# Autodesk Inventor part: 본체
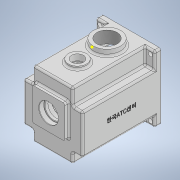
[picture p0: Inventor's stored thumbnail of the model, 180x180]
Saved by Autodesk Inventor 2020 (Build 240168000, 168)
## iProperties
Created: 2022-01
Part Number: 본체
Material: 일반
Document SubType Name: Modeling
Designer: user
Density: 1 g/cm^3
Appearance: 기본값
Author: user
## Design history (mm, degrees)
sketch "스케치21"
  geometry: 1 further point
sketch "스케치30"
  geometry: L1 (49, -55)-(-49, -55); L2 (-49, -55)-(-49, 55); L3 (-49, 55)-(49, 55); L4 (49, 55)-(49, -55); L5 (49, -55)-(-49, 55); L6 (-49, -55)-(49, 55); 1 further point
  constraints: 12 end point, 2 midpoint, 2 parallel, 1 horizontal, 1 perpendicular
  dimensions: "d101" = 98 distance of L2.end L3.end; "d102" = 110 distance of L1.end L2.end
extrude "돌출16" new body sketch "스케치30" stored distance "d103" = 130; taper "d104" = 0 deg
sketch "스케치31" dims "d106" = 84
  geometry: L1 (49, -55)-(-49, -55) reference; L2 (0, -55)-(0, -5); L3 (0, -5)-(0, 45); L4 (0, 45)-(-23, 45); L5 (-23, 45)-(23, 45); L6 (23, 45)-(23, 30.143); L7 (23, 30.143)-(-23, 30.143); L8 (-23, 30.143)-(-23, 45); L9 (26, 27.143)-(26, 48); L10 (26, 48)-(-26, 48); L11 (-26, 48)-(-26, 27.143); L12 (-26, 27.143)-(26, 27.143); C1 r 45 at (0, -5); 3 further points
  constraints: 22 end point, 4 parallel, 3 perpendicular, 2 vertical, 1 centre point, 1 coincident, 1 horizontal, 1 midpoint, 6 other
  dimensions: "d105" = 50 distance of L2.start L2.end; "d107" = 50 distance of L3.start L3.end; "d108" = 23 distance of L3.end L4.end; "d109" = 46 distance of L6.end L7.end; "d110" = 3 distance between parallel lines of L6 L9; "d111" = 3 dimension on C1
extrude "돌출17" cut sketch "스케치31" distance "d112" = 9; taper "d113" = 0 deg
sketch "스케치32" dims "d115" = 84
  geometry: L1 (-49, -55)-(49, -55) reference; L2 (0, -55)-(0, -5); L3 (0, -5)-(0, 45); L4 (0, 45)-(-23, 45); L5 (-23, 45)-(23, 45); L6 (23, 45)-(23, 30.143); L7 (23, 30.143)-(-23, 30.143); L8 (-23, 30.143)-(-23, 45); 3 further points
  constraints: 14 end point, 2 parallel, 2 perpendicular, 2 vertical, 1 coincident, 1 horizontal, 1 midpoint, 3 other
  dimensions: "d114" = 50 distance of L2.start L2.end; "d116" = 50 distance of L3.start L3.end; "d117" = 23 distance of L3.end L4.end; "d118" = 46 distance of L6.end L7.end
extrude "돌출18" cut sketch "스케치32" distance "d119" = 112; taper "d120" = 0 deg
sketch "스케치33"
  geometry: L1 (-49, -55)-(49, -55) reference; L2 (0, -55)-(0, -5); L3 (0, -5)-(0, 6); L4 (0, -5)-(0, -25); C1 r 21 at (0, 6); C2 r 15 at (0, -25); 3 further points
  constraints: 6 end point, 2 centre point, 2 coincident, 2 point on line, 1 midpoint, 1 vertical
  dimensions: "d121" = 50 distance of L2.start L2.end; "d122" = 11 distance of L2.end L3.end; "d123" = 20 distance of L2.end L4.end; "d124" = 42 diameter of C1; "d125" = 30 diameter of C2
extrude "돌출19" join sketch "스케치33" distance "d126" = 7; taper "d127" = 0 deg
sketch "스케치34"
  geometry: L1 (-49, 55)-(-49, -55) reference; L2 (-49, 55)-(-33, 55); L3 (-33, 55)-(-33, 28); L4 (-33, 28)-(-49, 28); L5 (-49, 28)-(-49, 55); L6 (-49, -55)-(49, -55) reference; L7 (-49, -55)-(-33, -55); L8 (-33, -55)-(-33, -38); L9 (-33, -38)-(-49, -38); L10 (-49, -38)-(-49, -55); L11 (49, -55)-(33, -55); L12 (33, -55)-(33, -38); L13 (33, -38)-(49, -38); L14 (49, -38)-(49, -55); L15 (49, 55)-(-49, 55) reference; L16 (49, 55)-(33, 55); L17 (33, 55)-(33, 28); L18 (33, 28)-(49, 28); L19 (49, 28)-(49, 55); 6 further points
  constraints: 32 end point, 8 parallel, 4 horizontal, 4 perpendicular
  dimensions: "d128" = 16 distance of L3.end L4.end; "d129" = 27 distance of L2.end L3.end; "d130" = 16 distance of L9.end L8.end; "d131" = 17 distance of L8.end L7.end; "d132" = 16 distance of L12.end L13.end; "d133" = 17 distance of L11.end L12.end; "d134" = 16 distance of L18.end L17.end; "d135" = 27 distance of L17.end L16.end
extrude "돌출20" cut sketch "스케치34" distance "d136" = 120; taper "d137" = 0 deg
sketch "스케치35"
  geometry: L1 (98, 0)-(0, 0) reference; L2 (49, 0)-(49, -40); L3 (49, -40)-(49, -89); C1 r 15 at (49, -89); C2 r 22.5 at (49, -40); 1 further point
  constraints: 4 end point, 2 centre point, 2 coincident, 1 midpoint, 1 point on line, 1 vertical
  dimensions: "d138" = 40 distance of L2.start L2.end; "d139" = 49 distance of L2.end L3.end; "d140" = 30 diameter of C1; "d141" = 45 diameter of C2
extrude "돌출21" join sketch "스케치35" distance "d142" = 5; taper "d143" = 0 deg
extrude "돌출22" join sketch "스케치35" distance "d144" = 10; taper "d145" = 0 deg
sketch "스케치36"
  geometry: C1 r 15 at (0, 0) reference; C2 r 10 at (0, 0); 1 further point
  constraints: 1 centre point, 1 coincident
  dimensions: "d146" = 20 diameter of C2
extrude "돌출23" cut sketch "스케치36" distance "d147" = 20; taper "d148" = 0 deg
sketch "스케치37"
  geometry: C1 r 10 at (23, 80) reference; C2 r 15 at (23, 80); 1 further point
  constraints: 1 centre point, 1 coincident
  dimensions: "d149" = 30 diameter of C2
extrude "돌출24" cut sketch "스케치37" distance "d150" = 5; taper "d151" = 0 deg
sketch "스케치38"
  geometry: 1 further point
sketch "스케치39"
  geometry: C1 r 22.5 at (0, 0) reference; 2 further points
  constraints: 1 coincident
hole "구멍4" sketch "스케치39" at (0, 0) diameter "d152" = 33.376; stored, may be unused: countersink angle "d156" = 90 deg, drill point angle "d158" = 118 deg; dims "d153" = 70, "d154" = 4, "d155" = 2, "d157" = 77.3
sketch "스케치40" dims "d162" = 8
  geometry: L1 (-49, -55)-(49, -55) reference; L2 (0, -55)-(0, -5); L3 (36, -1)-(41.644, -1); L4 (4, -9)-(-4, -9); L5 (-4, -9)-(-4, -1); L6 (-4, -1)-(4, -1); L7 (4, -1)-(4, -9); L8 (4, -9)-(-4, -1); L9 (-4, -9)-(4, -1); L10 (-4, -1)-(-47.386, -1); L11 (-4, -9)-(-49, -9); L12 (-49, -38)-(-49, 28) reference; L13 (4, -9)-(44.822, -9); L14 (4, -1)-(44.822, -1); C1 r 4 at (-36, -5); C2 r 42 at (0, -5); A1 r 36 centre (0, -5) between (-36, -5) and (36, -5); A2 r 45 centre (0, -5) between (-26, 31.729) and (26, 31.729) reference; A3 r 42 centre (0, -5) between (-23, 30.143) and (23, 30.143) reference; 7 further points
  constraints: 24 end point, 5 horizontal, 4 point on circle, 3 centre point, 3 midpoint, 3 point on line, 2 coincident, 2 horizontal alignment, 2 parallel, 1 concentric, 1 perpendicular, 1 vertical, 3 other
  dimensions: "d159" = 50 distance of L2.start L2.end; "d160" = 72 diameter of A1; "d161" = 8 diameter of C1; "d163" = 8 distance of L5.end L6.end; "d164" = 8 distance of L4.end L5.end
extrude "돌출25" join sketch "스케치40" distance "d165" = 121; taper "d166" = 0 deg
sketch "스케치41"
  geometry: L1 (42, -48)-(-42, -48); L2 (-42, -48)-(-42, 48); L3 (-42, 48)-(42, 48); L4 (42, 48)-(42, -48); L5 (42, -48)-(-42, 48); L6 (-42, -48)-(42, 48); 1 further point
  constraints: 12 end point, 2 midpoint, 2 parallel, 1 horizontal, 1 perpendicular
  dimensions: "d167" = 84 distance of L2.end L3.end; "d168" = 96 distance of L1.end L2.end
hole "구멍5" sketch "스케치41" at (-42, 48), (-42, -48), (42, -48), (42, 48) diameter "d169" = 7; stored, may be unused: countersink angle "d173" = 90 deg, drill point angle "d175" = 118 deg; dims "d170" = 70, "d171" = 4, "d172" = 2, "d174" = 77.3
sketch "스케치42"
  geometry: A1 r 4 centre (-36, -5) between (-36, -9) and (-36, -1) reference; A2 r 4 centre (36, -5) between (36, -1) and (36, -9) reference; 3 further points
  constraints: 2 coincident
hole "구멍6" sketch "스케치42" at (-36, -5), (36, -5) diameter "d176" = 3.242; stored, may be unused: countersink angle "d180" = 90 deg, drill point angle "d182" = 118 deg; dims "d177" = 7, "d178" = 4, "d179" = 2, "d181" = 9
sketch "스케치46"
  geometry: A1 r 21 centre (0, 6) between (8.978, -12.984) and (-8.978, -12.984) reference; 2 further points
  constraints: 1 coincident
hole "구멍7" sketch "스케치46" at (0, 6) diameter "d188" = 28; stored, may be unused: countersink angle "d192" = 90 deg, drill point angle "d194" = 118 deg; dims "d189" = 7, "d190" = 35, "d191" = 10, "d193" = 9
sketch "스케치47"
  geometry: A1 r 15 centre (0, -25) between (-8.978, -12.984) and (8.978, -12.984) reference; 2 further points
  constraints: 1 coincident
hole "구멍8" sketch "스케치47" at (0, -25) diameter "d195" = 19; stored, may be unused: countersink angle "d199" = 90 deg, drill point angle "d201" = 0 deg; dims "d196" = 7, "d197" = 22, "d198" = 7, "d200" = 10
sketch "스케치49"
  geometry: L1 (-27, -21)-(27, -21); L2 (27, -21)-(27, 33); L3 (27, 33)-(-27, 33); L4 (-27, 33)-(-27, -21); L5 (-27, -21)-(27, 33); L6 (27, -21)-(-27, 33); C1 r 16 at (0, 6) reference; 1 further point
  constraints: 12 end point, 2 midpoint, 2 parallel, 1 horizontal, 1 perpendicular
  dimensions: "d205" = 54 distance of L3.end L2.end; "d206" = 54 distance of L2.end L1.end
sketch "스케치52" dims "d105" = 50, "d106" = 84, "d107" = 50, "d108" = 23, "d109" = 46, "d110" = 3, "d111" = 3
  geometry: L1 (-130, 17)-(-130, 83) reference; L2 (-10, 83)-(-130, 83) reference; 2 further points
  constraints: 1 other
  dimensions: "d209" = 65 distance from line of L1 point (-65, 50); "d210" = 33 distance from line of L2 point (-65, 50)
fillet "모깎기2" dims "d215" = 3
fillet "모깎기3" dims "d216" = 3
fillet "모깎기4" dims "d217" = 3
fillet "모깎기5" dims "d218" = 3
fillet "모깎기6" dims "d219" = 3
fillet "모깎기7" dims "d223" = 3
fillet "모깎기8" dims "d224" = 3
fillet "모깎기9" dims "d225" = 3
fillet "모깎기10" dims "d226" = 0.3
chamfer "모따기3" distance "d227" = 1; stored, may be unused: second distance "d228" = 2, angle "d229" = 45 deg
fillet "모깎기11" dims "d230" = 6
fillet "모깎기12" dims "d231" = 3
chamfer "모따기4" distance "d232" = 1; stored, may be unused: second distance "d233" = 2, angle "d234" = 45 deg
feature "엠보싱1" dims "d105" = 50, "d106" = 84, "d107" = 50, "d108" = 23, "d109" = 46, "d110" = 3, "d111" = 3, "d235" = 0.5, "d236" = 0
extrude "돌출28" join sketch "스케치49" distance "d243" = 7; taper "d244" = 0 deg
sketch "스케치56"
  geometry: L1 (27, -21)-(27, 33) reference; L2 (-27, -21)-(27, -21) reference; C1 r 16 at (0, 6); 3 further points
  constraints: 2 midpoint, 1 centre point, 1 horizontal alignment, 1 vertical alignment
  dimensions: "d245" = 32 diameter of C1
extrude "돌출29" cut sketch "스케치56" distance "d246" = 8.3; taper "d247" = 0 deg
chamfer "모따기7" distance "d248" = 0.8; stored, may be unused: second distance "d249" = 2, angle "d250" = 30 deg
fillet "모깎기13" dims "d254" = 3
fillet "모깎기14" dims "d255" = 3
fillet "모깎기16" dims "d257" = 0.3
fillet "모깎기17" dims "d258" = 0.3
node "솔리드2"
feature "A9D066F2-1C7D-4E18-AEED-F7BC21143FA4" dims "d169" = 7, "d170" = 70, "d171" = 4, "d172" = 2, "d173" = 90 deg, "d174" = 77.3, "d175" = 118 deg
